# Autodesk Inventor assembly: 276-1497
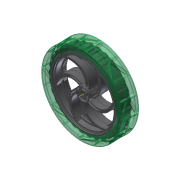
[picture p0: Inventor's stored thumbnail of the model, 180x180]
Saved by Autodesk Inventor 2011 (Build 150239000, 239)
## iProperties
Company: Autodesk Inc.
Created: 2010-06
Part Number: 276-1497
Document SubType Name: Assembly
Designer: Autodesk Inc.
Catalog Web Link: http://www.vexrobotics.com/products/accessories/motion/276-1497.html
Description: VEX 4" diameter wheel. This wheel includes a tire which works well on any surface.
Vendor: Innovation First, Inc.
Author: Autodesk Inc.
Title: VEX Robotics Kit of Parts
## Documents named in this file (3)
- D:\@VEX\BZ-Parts Kit\Motion\Medium Wheel.iam
- D:\@VEX\BZ-Parts Kit\Motion\Medium Wheel Hub.ipt
- D:\@VEX\BZ-Parts Kit\Motion\Medium Wheel Tire.ipt
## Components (2 placed, 2 different names)
1. Medium Wheel Hub:1 — Mate:1, Mate:2, Angle:1
2. Medium Wheel Tire:1 — Mate:1, Mate:2, Angle:1
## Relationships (3: Mate 2, Angle 1)
- Mate:1: Medium Wheel Hub:1 ↔ Medium Wheel Tire:1
- Mate:2: Medium Wheel Hub:1 ↔ Medium Wheel Tire:1
- Angle:1: Medium Wheel Hub:1 ↔ Medium Wheel Tire:1
